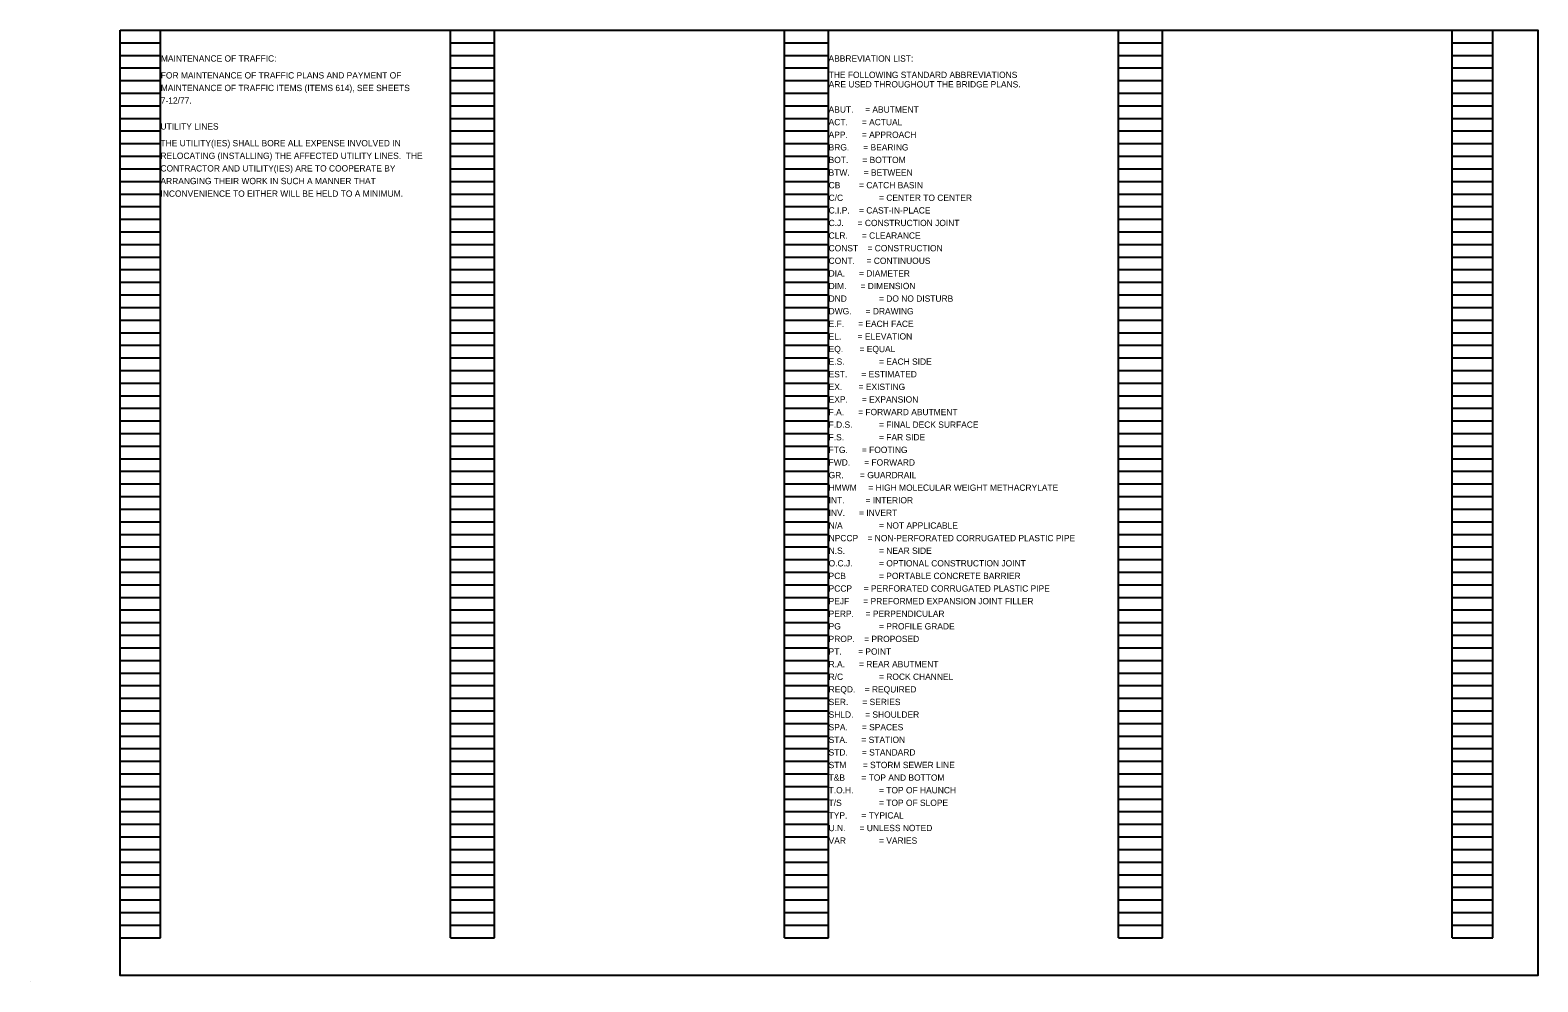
# Model space of a CAD drawing. Extents: x 8.9 to 72, y -18.6 to 3.4.
# Drawn here: x 8.86 to 42.36, y -18.57 to 2.57 of the extents above; entities that cross this region are included whole.
import ezdxf

# ---------------------------------------------------------------- set-up
doc = ezdxf.new("R2010")
doc.units = 0
for name, color, linetype in [('BR_P_Gen_Text', 7, 'Continuous'), ('Default', 7, 'Continuous'), ('SC_Scratch1', 7, 'Continuous'), ('SH_Data', 7, 'Continuous')]:
    doc.layers.add(name, color=color, linetype=linetype)

msp = doc.modelspace()

# ---------------------------------------------------------------- linework, layer by layer
at = {"layer": 'SC_Scratch1'}
msp.add_lwpolyline([(10.858, 2.575), (42.358, 2.575), (42.358, -18.425), (10.858, -18.425)], close=True, dxfattribs=at)
at = {"layer": 'SH_Data'}
for p, q in [((10.858, -17.585), (10.858, 2.575)), ((10.858, 2.575), (11.758, 2.575)), ((11.758, -17.585), (11.758, 2.575)), ((18.198, -17.585), (18.198, 2.575)), ((18.198, 2.575), (19.178, 2.575)), ((19.178, -17.585), (19.178, 2.575)), ((25.618, -17.585), (25.618, 2.575)), ((25.618, 2.575), (26.598, 2.575)), ((26.598, -17.585), (26.598, 2.575)), ((33.038, -17.585), (33.038, 2.575)), ((33.038, 2.575), (34.018, 2.575)), ((34.018, -17.585), (34.018, 2.575)), ((40.458, -17.585), (40.458, 2.575)), ((40.458, 2.575), (41.358, 2.575)), ((41.358, -17.585), (41.358, 2.575)), ((10.858, 2.295), (11.758, 2.295)), ((10.858, 2.015), (11.758, 2.015)), ((18.198, 2.295), (19.178, 2.295)), ((18.198, 2.015), (19.178, 2.015)), ((25.618, 2.295), (26.598, 2.295)), ((25.618, 2.015), (26.598, 2.015)), ((33.038, 2.295), (34.018, 2.295)), ((33.038, 2.015), (34.018, 2.015)), ((40.458, 2.295), (41.358, 2.295)), ((40.458, 2.015), (41.358, 2.015)), ((10.858, 1.735), (11.758, 1.735)), ((18.198, 1.735), (19.178, 1.735)), ((25.618, 1.735), (26.598, 1.735)), ((33.038, 1.735), (34.018, 1.735)), ((40.458, 1.735), (41.358, 1.735)), ((10.858, 1.455), (11.758, 1.455)), ((18.198, 1.455), (19.178, 1.455)), ((25.618, 1.455), (26.598, 1.455)), ((33.038, 1.455), (34.018, 1.455)), ((40.458, 1.455), (41.358, 1.455)), ((10.858, 1.175), (11.758, 1.175)), ((18.198, 1.175), (19.178, 1.175)), ((25.618, 1.175), (26.598, 1.175)), ((33.038, 1.175), (34.018, 1.175)), ((40.458, 1.175), (41.358, 1.175)), ((10.858, 0.895), (11.758, 0.895)), ((18.198, 0.895), (19.178, 0.895)), ((25.618, 0.895), (26.598, 0.895)), ((33.038, 0.895), (34.018, 0.895)), ((40.458, 0.895), (41.358, 0.895)), ((10.858, 0.615), (11.758, 0.615)), ((18.198, 0.615), (19.178, 0.615)), ((25.618, 0.615), (26.598, 0.615)), ((33.038, 0.615), (34.018, 0.615)), ((40.458, 0.615), (41.358, 0.615)), ((10.858, 0.335), (11.758, 0.335)), ((10.858, 0.055), (11.758, 0.055)), ((18.198, 0.335), (19.178, 0.335)), ((18.198, 0.055), (19.178, 0.055)), ((25.618, 0.335), (26.598, 0.335)), ((25.618, 0.055), (26.598, 0.055)), ((33.038, 0.335), (34.018, 0.335)), ((33.038, 0.055), (34.018, 0.055)), ((40.458, 0.335), (41.358, 0.335)), ((40.458, 0.055), (41.358, 0.055)), ((10.858, -0.225), (11.758, -0.225)), ((18.198, -0.225), (19.178, -0.225)), ((25.618, -0.225), (26.598, -0.225)), ((33.038, -0.225), (34.018, -0.225)), ((40.458, -0.225), (41.358, -0.225)), ((10.858, -0.505), (11.758, -0.505)), ((18.198, -0.505), (19.178, -0.505)), ((25.618, -0.505), (26.598, -0.505)), ((33.038, -0.505), (34.018, -0.505)), ((40.458, -0.505), (41.358, -0.505)), ((10.858, -0.785), (11.758, -0.785)), ((18.198, -0.785), (19.178, -0.785)), ((25.618, -0.785), (26.598, -0.785)), ((33.038, -0.785), (34.018, -0.785)), ((40.458, -0.785), (41.358, -0.785)), ((10.858, -1.065), (11.758, -1.065)), ((18.198, -1.065), (19.178, -1.065)), ((25.618, -1.065), (26.598, -1.065)), ((33.038, -1.065), (34.018, -1.065)), ((40.458, -1.065), (41.358, -1.065)), ((10.858, -1.345), (11.758, -1.345)), ((10.858, -1.625), (11.758, -1.625)), ((18.198, -1.345), (19.178, -1.345)), ((18.198, -1.625), (19.178, -1.625)), ((25.618, -1.345), (26.598, -1.345)), ((25.618, -1.625), (26.598, -1.625)), ((33.038, -1.345), (34.018, -1.345)), ((33.038, -1.625), (34.018, -1.625)), ((40.458, -1.345), (41.358, -1.345)), ((40.458, -1.625), (41.358, -1.625)), ((10.858, -1.905), (11.758, -1.905)), ((18.198, -1.905), (19.178, -1.905)), ((25.618, -1.905), (26.598, -1.905)), ((33.038, -1.905), (34.018, -1.905)), ((40.458, -1.905), (41.358, -1.905)), ((10.858, -2.185), (11.758, -2.185)), ((18.198, -2.185), (19.178, -2.185)), ((25.618, -2.185), (26.598, -2.185)), ((33.038, -2.185), (34.018, -2.185)), ((40.458, -2.185), (41.358, -2.185)), ((10.858, -2.465), (11.758, -2.465)), ((18.198, -2.465), (19.178, -2.465)), ((25.618, -2.465), (26.598, -2.465)), ((33.038, -2.465), (34.018, -2.465)), ((40.458, -2.465), (41.358, -2.465)), ((10.858, -2.745), (11.758, -2.745)), ((18.198, -2.745), (19.178, -2.745)), ((25.618, -2.745), (26.598, -2.745)), ((33.038, -2.745), (34.018, -2.745)), ((40.458, -2.745), (41.358, -2.745)), ((10.858, -3.025), (11.758, -3.025)), ((10.858, -3.305), (11.758, -3.305)), ((18.198, -3.025), (19.178, -3.025)), ((18.198, -3.305), (19.178, -3.305)), ((25.618, -3.025), (26.598, -3.025)), ((25.618, -3.305), (26.598, -3.305)), ((33.038, -3.025), (34.018, -3.025)), ((33.038, -3.305), (34.018, -3.305)), ((40.458, -3.025), (41.358, -3.025)), ((40.458, -3.305), (41.358, -3.305)), ((10.858, -3.585), (11.758, -3.585)), ((18.198, -3.585), (19.178, -3.585)), ((25.618, -3.585), (26.598, -3.585)), ((33.038, -3.585), (34.018, -3.585)), ((40.458, -3.585), (41.358, -3.585)), ((10.858, -3.865), (11.758, -3.865)), ((18.198, -3.865), (19.178, -3.865)), ((25.618, -3.865), (26.598, -3.865)), ((33.038, -3.865), (34.018, -3.865)), ((40.458, -3.865), (41.358, -3.865)), ((10.858, -4.145), (11.758, -4.145)), ((18.198, -4.145), (19.178, -4.145)), ((25.618, -4.145), (26.598, -4.145)), ((33.038, -4.145), (34.018, -4.145)), ((40.458, -4.145), (41.358, -4.145)), ((10.858, -4.425), (11.758, -4.425)), ((18.198, -4.425), (19.178, -4.425)), ((25.618, -4.425), (26.598, -4.425)), ((33.038, -4.425), (34.018, -4.425)), ((40.458, -4.425), (41.358, -4.425)), ((10.858, -4.705), (11.758, -4.705)), ((10.858, -4.985), (11.758, -4.985)), ((18.198, -4.705), (19.178, -4.705)), ((18.198, -4.985), (19.178, -4.985)), ((25.618, -4.705), (26.598, -4.705)), ((25.618, -4.985), (26.598, -4.985)), ((33.038, -4.705), (34.018, -4.705)), ((33.038, -4.985), (34.018, -4.985)), ((40.458, -4.705), (41.358, -4.705)), ((40.458, -4.985), (41.358, -4.985)), ((10.858, -5.265), (11.758, -5.265)), ((18.198, -5.265), (19.178, -5.265)), ((25.618, -5.265), (26.598, -5.265)), ((33.038, -5.265), (34.018, -5.265)), ((40.458, -5.265), (41.358, -5.265)), ((10.858, -5.545), (11.758, -5.545)), ((18.198, -5.545), (19.178, -5.545)), ((25.618, -5.545), (26.598, -5.545)), ((33.038, -5.545), (34.018, -5.545)), ((40.458, -5.545), (41.358, -5.545)), ((10.858, -5.825), (11.758, -5.825)), ((18.198, -5.825), (19.178, -5.825)), ((25.618, -5.825), (26.598, -5.825)), ((33.038, -5.825), (34.018, -5.825)), ((40.458, -5.825), (41.358, -5.825)), ((10.858, -6.105), (11.758, -6.105)), ((18.198, -6.105), (19.178, -6.105)), ((25.618, -6.105), (26.598, -6.105)), ((33.038, -6.105), (34.018, -6.105)), ((40.458, -6.105), (41.358, -6.105)), ((10.858, -6.385), (11.758, -6.385)), ((10.858, -6.665), (11.758, -6.665)), ((18.198, -6.385), (19.178, -6.385)), ((18.198, -6.665), (19.178, -6.665)), ((25.618, -6.385), (26.598, -6.385)), ((25.618, -6.665), (26.598, -6.665)), ((33.038, -6.385), (34.018, -6.385)), ((33.038, -6.665), (34.018, -6.665)), ((40.458, -6.385), (41.358, -6.385)), ((40.458, -6.665), (41.358, -6.665)), ((10.858, -6.945), (11.758, -6.945)), ((18.198, -6.945), (19.178, -6.945)), ((25.618, -6.945), (26.598, -6.945)), ((33.038, -6.945), (34.018, -6.945)), ((40.458, -6.945), (41.358, -6.945)), ((10.858, -7.225), (11.758, -7.225)), ((18.198, -7.225), (19.178, -7.225)), ((25.618, -7.225), (26.598, -7.225)), ((33.038, -7.225), (34.018, -7.225)), ((40.458, -7.225), (41.358, -7.225)), ((10.858, -7.505), (11.758, -7.505)), ((18.198, -7.505), (19.178, -7.505)), ((25.618, -7.505), (26.598, -7.505)), ((33.038, -7.505), (34.018, -7.505)), ((40.458, -7.505), (41.358, -7.505)), ((10.858, -7.785), (11.758, -7.785)), ((18.198, -7.785), (19.178, -7.785)), ((25.618, -7.785), (26.598, -7.785)), ((33.038, -7.785), (34.018, -7.785)), ((40.458, -7.785), (41.358, -7.785)), ((10.858, -8.065), (11.758, -8.065)), ((10.858, -8.345), (11.758, -8.345)), ((18.198, -8.065), (19.178, -8.065)), ((18.198, -8.345), (19.178, -8.345)), ((25.618, -8.065), (26.598, -8.065)), ((25.618, -8.345), (26.598, -8.345)), ((33.038, -8.065), (34.018, -8.065)), ((33.038, -8.345), (34.018, -8.345)), ((40.458, -8.065), (41.358, -8.065)), ((40.458, -8.345), (41.358, -8.345)), ((10.858, -8.625), (11.758, -8.625)), ((18.198, -8.625), (19.178, -8.625)), ((25.618, -8.625), (26.598, -8.625)), ((33.038, -8.625), (34.018, -8.625)), ((40.458, -8.625), (41.358, -8.625)), ((10.858, -8.905), (11.758, -8.905)), ((18.198, -8.905), (19.178, -8.905)), ((25.618, -8.905), (26.598, -8.905)), ((33.038, -8.905), (34.018, -8.905)), ((40.458, -8.905), (41.358, -8.905)), ((10.858, -9.185), (11.758, -9.185)), ((18.198, -9.185), (19.178, -9.185)), ((25.618, -9.185), (26.598, -9.185)), ((33.038, -9.185), (34.018, -9.185)), ((40.458, -9.185), (41.358, -9.185)), ((10.858, -9.465), (11.758, -9.465)), ((18.198, -9.465), (19.178, -9.465)), ((25.618, -9.465), (26.598, -9.465)), ((33.038, -9.465), (34.018, -9.465)), ((40.458, -9.465), (41.358, -9.465)), ((10.858, -9.745), (11.758, -9.745)), ((10.858, -10.025), (11.758, -10.025)), ((18.198, -9.745), (19.178, -9.745)), ((18.198, -10.025), (19.178, -10.025)), ((25.618, -9.745), (26.598, -9.745)), ((25.618, -10.025), (26.598, -10.025)), ((33.038, -9.745), (34.018, -9.745)), ((33.038, -10.025), (34.018, -10.025)), ((40.458, -9.745), (41.358, -9.745)), ((40.458, -10.025), (41.358, -10.025)), ((10.858, -10.305), (11.758, -10.305)), ((18.198, -10.305), (19.178, -10.305)), ((25.618, -10.305), (26.598, -10.305)), ((33.038, -10.305), (34.018, -10.305)), ((40.458, -10.305), (41.358, -10.305)), ((10.858, -10.585), (11.758, -10.585)), ((18.198, -10.585), (19.178, -10.585)), ((25.618, -10.585), (26.598, -10.585)), ((33.038, -10.585), (34.018, -10.585)), ((40.458, -10.585), (41.358, -10.585)), ((10.858, -10.865), (11.758, -10.865)), ((18.198, -10.865), (19.178, -10.865)), ((25.618, -10.865), (26.598, -10.865)), ((33.038, -10.865), (34.018, -10.865)), ((40.458, -10.865), (41.358, -10.865)), ((10.858, -11.145), (11.758, -11.145)), ((18.198, -11.145), (19.178, -11.145)), ((25.618, -11.145), (26.598, -11.145)), ((33.038, -11.145), (34.018, -11.145)), ((40.458, -11.145), (41.358, -11.145)), ((10.858, -11.425), (11.758, -11.425)), ((10.858, -11.705), (11.758, -11.705)), ((18.198, -11.425), (19.178, -11.425)), ((18.198, -11.705), (19.178, -11.705)), ((25.618, -11.425), (26.598, -11.425)), ((25.618, -11.705), (26.598, -11.705)), ((33.038, -11.425), (34.018, -11.425)), ((33.038, -11.705), (34.018, -11.705)), ((40.458, -11.425), (41.358, -11.425)), ((40.458, -11.705), (41.358, -11.705)), ((10.858, -11.985), (11.758, -11.985)), ((18.198, -11.985), (19.178, -11.985)), ((25.618, -11.985), (26.598, -11.985)), ((33.038, -11.985), (34.018, -11.985)), ((40.458, -11.985), (41.358, -11.985)), ((10.858, -12.265), (11.758, -12.265)), ((18.198, -12.265), (19.178, -12.265)), ((25.618, -12.265), (26.598, -12.265)), ((33.038, -12.265), (34.018, -12.265)), ((40.458, -12.265), (41.358, -12.265)), ((10.858, -12.545), (11.758, -12.545)), ((18.198, -12.545), (19.178, -12.545)), ((25.618, -12.545), (26.598, -12.545)), ((33.038, -12.545), (34.018, -12.545)), ((40.458, -12.545), (41.358, -12.545)), ((10.858, -12.825), (11.758, -12.825)), ((18.198, -12.825), (19.178, -12.825)), ((25.618, -12.825), (26.598, -12.825)), ((33.038, -12.825), (34.018, -12.825)), ((40.458, -12.825), (41.358, -12.825)), ((10.858, -13.105), (11.758, -13.105)), ((10.858, -13.385), (11.758, -13.385)), ((18.198, -13.105), (19.178, -13.105)), ((18.198, -13.385), (19.178, -13.385)), ((25.618, -13.105), (26.598, -13.105)), ((25.618, -13.385), (26.598, -13.385)), ((33.038, -13.105), (34.018, -13.105)), ((33.038, -13.385), (34.018, -13.385)), ((40.458, -13.105), (41.358, -13.105)), ((40.458, -13.385), (41.358, -13.385)), ((10.858, -13.665), (11.758, -13.665)), ((18.198, -13.665), (19.178, -13.665)), ((25.618, -13.665), (26.598, -13.665)), ((33.038, -13.665), (34.018, -13.665)), ((40.458, -13.665), (41.358, -13.665)), ((10.858, -13.945), (11.758, -13.945)), ((18.198, -13.945), (19.178, -13.945)), ((25.618, -13.945), (26.598, -13.945)), ((33.038, -13.945), (34.018, -13.945)), ((40.458, -13.945), (41.358, -13.945)), ((10.858, -14.225), (11.758, -14.225)), ((18.198, -14.225), (19.178, -14.225)), ((25.618, -14.225), (26.598, -14.225)), ((33.038, -14.225), (34.018, -14.225)), ((40.458, -14.225), (41.358, -14.225)), ((10.858, -14.505), (11.758, -14.505)), ((18.198, -14.505), (19.178, -14.505)), ((25.618, -14.505), (26.598, -14.505)), ((33.038, -14.505), (34.018, -14.505)), ((40.458, -14.505), (41.358, -14.505)), ((10.858, -14.785), (11.758, -14.785)), ((10.858, -15.065), (11.758, -15.065)), ((18.198, -14.785), (19.178, -14.785)), ((18.198, -15.065), (19.178, -15.065)), ((25.618, -14.785), (26.598, -14.785)), ((25.618, -15.065), (26.598, -15.065)), ((33.038, -14.785), (34.018, -14.785)), ((33.038, -15.065), (34.018, -15.065)), ((40.458, -14.785), (41.358, -14.785)), ((40.458, -15.065), (41.358, -15.065)), ((10.858, -15.345), (11.758, -15.345)), ((18.198, -15.345), (19.178, -15.345)), ((25.618, -15.345), (26.598, -15.345)), ((33.038, -15.345), (34.018, -15.345)), ((40.458, -15.345), (41.358, -15.345)), ((10.858, -15.625), (11.758, -15.625)), ((18.198, -15.625), (19.178, -15.625)), ((25.618, -15.625), (26.598, -15.625)), ((33.038, -15.625), (34.018, -15.625)), ((40.458, -15.625), (41.358, -15.625)), ((10.858, -15.905), (11.758, -15.905)), ((18.198, -15.905), (19.178, -15.905)), ((25.618, -15.905), (26.598, -15.905)), ((33.038, -15.905), (34.018, -15.905)), ((40.458, -15.905), (41.358, -15.905)), ((10.858, -16.185), (11.758, -16.185)), ((18.198, -16.185), (19.178, -16.185)), ((25.618, -16.185), (26.598, -16.185)), ((33.038, -16.185), (34.018, -16.185)), ((40.458, -16.185), (41.358, -16.185)), ((10.858, -16.465), (11.758, -16.465)), ((10.858, -16.745), (11.758, -16.745)), ((18.198, -16.465), (19.178, -16.465)), ((18.198, -16.745), (19.178, -16.745)), ((25.618, -16.465), (26.598, -16.465)), ((25.618, -16.745), (26.598, -16.745)), ((33.038, -16.465), (34.018, -16.465)), ((33.038, -16.745), (34.018, -16.745)), ((40.458, -16.465), (41.358, -16.465)), ((40.458, -16.745), (41.358, -16.745)), ((10.858, -17.025), (11.758, -17.025)), ((18.198, -17.025), (19.178, -17.025)), ((25.618, -17.025), (26.598, -17.025)), ((33.038, -17.025), (34.018, -17.025)), ((40.458, -17.025), (41.358, -17.025)), ((10.858, -17.305), (11.758, -17.305)), ((18.198, -17.305), (19.178, -17.305)), ((25.618, -17.305), (26.598, -17.305)), ((33.038, -17.305), (34.018, -17.305)), ((40.458, -17.305), (41.358, -17.305)), ((10.858, -17.585), (11.758, -17.585)), ((18.198, -17.585), (19.178, -17.585)), ((25.618, -17.585), (26.598, -17.585)), ((33.038, -17.585), (34.018, -17.585)), ((40.458, -17.585), (41.358, -17.585)), ((8.858, -18.565), (8.858, -18.565))]:
    msp.add_line(p, q, dxfattribs=at)

# ---------------------------------------------------------------- texts
at = {"layer": 'BR_P_Gen_Text'}
for s, p in [('MAINTENANCE OF TRAFFIC:', (11.763, 1.876)), ('ABBREVIATION LIST:', (26.598, 1.875)), ('FOR MAINTENANCE OF TRAFFIC PLANS AND PAYMENT OF ', (11.761, 1.501)), ('MAINTENANCE OF TRAFFIC ITEMS (ITEMS 614), SEE SHEETS ', (11.761, 1.221)), ('ARE USED THROUGHOUT THE BRIDGE PLANS.', (26.601, 1.302)), ('THE FOLLOWING STANDARD ABBREVIATIONS', (26.601, 1.512)), ('7-12/77.', (11.761, 0.941))]:
    msp.add_text(s, height=0.14, dxfattribs=at).set_placement(p)
for s, p in [('UTILITY LINES', (11.755, 0.367)), ('THE UTILITY(IES) SHALL BORE ALL EXPENSE INVOLVED IN ', (11.754, -0.005)), ('RELOCATING (INSTALLING) THE AFFECTED UTILITY LINES.  THE ', (11.754, -0.285)), ('CONTRACTOR AND UTILITY(IES) ARE TO COOPERATE BY ', (11.754, -0.565)), ('ARRANGING THEIR WORK IN SUCH A MANNER THAT ', (11.754, -0.846)), ('INCONVENIENCE TO EITHER WILL BE HELD TO A MINIMUM.', (11.754, -1.126))]:
    msp.add_text(s, height=0.14, rotation=0, dxfattribs=at).set_placement(p)
at = {"layer": 'Default'}
for s, p in [('ABUT.     = ABUTMENT', (26.6, 0.742)), ('ACT.      = ACTUAL', (26.6, 0.462)), ('APP.      = APPROACH', (26.6, 0.182)), ('BRG.      = BEARING', (26.6, -0.098)), ('BOT.      = BOTTOM', (26.6, -0.378)), ('BTW.      = BETWEEN', (26.6, -0.658)), ('CB        = CATCH BASIN', (26.6, -0.938)), ('C/C', (26.6, -1.218)), ('= CENTER TO CENTER', (27.72, -1.218)), ('C.I.P.    = CAST-IN-PLACE', (26.6, -1.498)), ('C.J.      = CONSTRUCTION JOINT', (26.6, -1.778)), ('CLR.      = CLEARANCE', (26.6, -2.058)), ('CONST    = CONSTRUCTION', (26.6, -2.338)), ('CONT.     = CONTINUOUS', (26.6, -2.618)), ('DIA.      = DIAMETER', (26.6, -2.898)), ('DIM.      = DIMENSION', (26.6, -3.178)), ('DND', (26.6, -3.458)), ('= DO NO DISTURB', (27.72, -3.458)), ('DWG.      = DRAWING', (26.6, -3.738)), ('E.F.      = EACH FACE', (26.6, -4.018)), ('EL.       = ELEVATION', (26.6, -4.298)), ('EQ.       = EQUAL', (26.6, -4.578)), ('E.S.', (26.6, -4.858)), ('EST.      = ESTIMATED', (26.6, -5.138)), ('= EACH SIDE', (27.72, -4.858)), ('EX.       = EXISTING', (26.6, -5.418)), ('EXP.      = EXPANSION', (26.6, -5.698)), ('F.A.      = FORWARD ABUTMENT', (26.6, -5.978)), ('F.D.S.', (26.6, -6.258)), ('= FINAL DECK SURFACE', (27.72, -6.258)), ('F.S.  ', (26.6, -6.538)), ('FTG.      = FOOTING', (26.6, -6.818)), ('= FAR SIDE', (27.72, -6.538)), ('FWD.      = FORWARD', (26.6, -7.098)), ('GR.       = GUARDRAIL', (26.6, -7.378)), ('HMWM     = HIGH MOLECULAR WEIGHT METHACRYLATE', (26.6, -7.658)), ('INT.', (26.6, -7.938)), ('     = INTERIOR', (27.16, -7.938)), ('N/A', (26.6, -8.498)), ('INV.      = INVERT', (26.6, -8.218)), ('= NOT APPLICABLE', (27.72, -8.498)), ('NPCCP    = NON-PERFORATED CORRUGATED PLASTIC PIPE', (26.6, -8.778)), ('N.S.', (26.6, -9.058)), ('= NEAR SIDE', (27.72, -9.058)), ('O.C.J.', (26.6, -9.338)), ('= OPTIONAL CONSTRUCTION JOINT', (27.72, -9.338)), ('PCB', (26.6, -9.618)), ('= PORTABLE CONCRETE BARRIER', (27.72, -9.618)), ('PCCP     = PERFORATED CORRUGATED PLASTIC PIPE', (26.6, -9.898)), ('PEJF      = PREFORMED EXPANSION JOINT FILLER', (26.6, -10.178)), ('PERP.     = PERPENDICULAR', (26.6, -10.458)), ('PG', (26.6, -10.738)), ('= PROFILE GRADE', (27.72, -10.738)), ('PROP.    = PROPOSED', (26.6, -11.018)), ('PT.       = POINT', (26.6, -11.298)), ('R.A.      = REAR ABUTMENT', (26.6, -11.578)), ('R/C', (26.6, -11.858)), ('= ROCK CHANNEL', (27.72, -11.858)), ('REQD.    = REQUIRED', (26.6, -12.138)), ('SER.      = SERIES', (26.6, -12.418)), ('SHLD.     = SHOULDER', (26.6, -12.698)), ('SPA.      = SPACES', (26.6, -12.978)), ('STA.      = STATION', (26.6, -13.258)), ('STD.      = STANDARD', (26.6, -13.538)), ('STM       = STORM SEWER LINE', (26.6, -13.818)), ('T&B       = TOP AND BOTTOM', (26.6, -14.098)), ('T.O.H.', (26.6, -14.378)), ('= TOP OF HAUNCH', (27.72, -14.378)), ('T/S', (26.6, -14.658)), ('= TOP OF SLOPE', (27.72, -14.658)), ('TYP.      = TYPICAL', (26.6, -14.938)), ('VAR', (26.6, -15.498)), ('U.N.      = UNLESS NOTED', (26.6, -15.218)), ('= VARIES', (27.72, -15.498))]:
    msp.add_text(s, height=0.14, rotation=0, dxfattribs=at).set_placement(p)

doc.saveas('drawing.dxf')
